Omron CX-Programmer project NuevoProyecto (CX-Programmer 9.50)

# PLC NewPLC1: CQM1 CPU21

## Program P5 (no task)
Local symbols
A 100.00 BOOL
ACP 100.07 BOOL
AL1 101.00 BOOL
AL2 101.01 BOOL
B 100.01 BOOL
Etapa_0 10.00 BOOL
Etapa_1 10.01 BOOL
Etapa_2 10.02 BOOL
Etapa_3 10.03 BOOL
Etapa_4 10.04 BOOL
Etapa_5 10.05 BOOL
Etapa_6 10.06 BOOL
Etapa_7 10.07 BOOL
Etapa_8 10.08 BOOL
FC1 0.03 BOOL
FC2 0.04 BOOL
LC 100.06 BOOL
LR_1 100.02 BOOL
LR_2 100.03 BOOL
LV1 100.04 BOOL
LV2 100.05 BOOL
S_1 0.01 BOOL
S_2 0.02 BOOL
T_0 15.00 BOOL
m 0.00 BOOL

### Section Sección1_Programa_principal
; Programa principal (Etapas 0 ... 8)

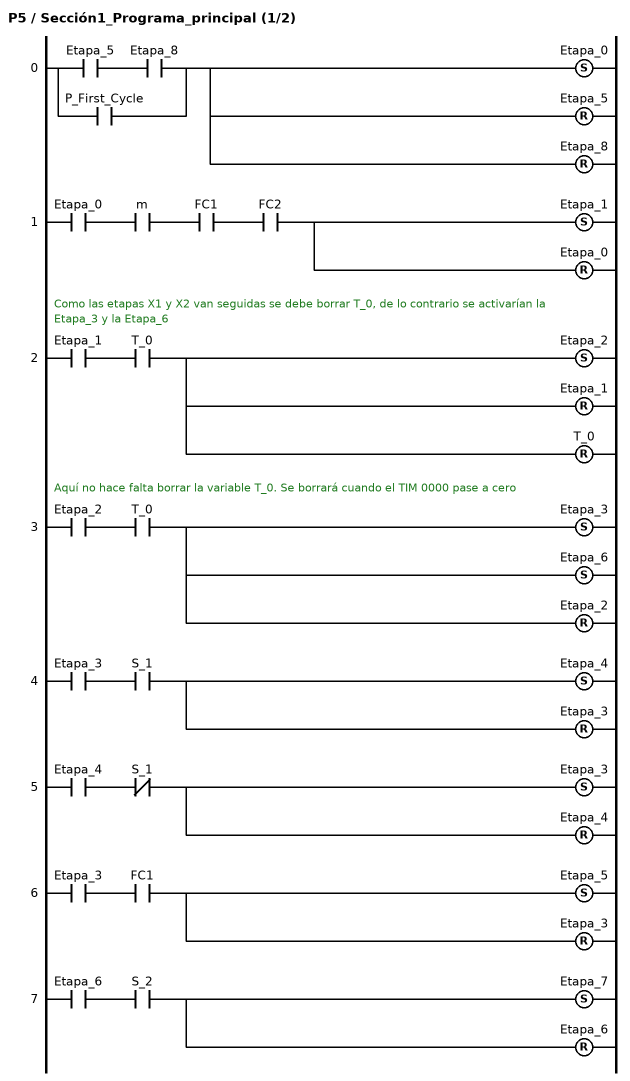
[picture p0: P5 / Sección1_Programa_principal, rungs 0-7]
; rung 0
LD Etapa_5
AND Etapa_8
OR P_First_Cycle
SET Etapa_0
RSET Etapa_5
RSET Etapa_8
; rung 1
LD Etapa_0
AND m
AND FC1
AND FC2
SET Etapa_1
RSET Etapa_0
; rung 2: Como las etapas X1 y X2 van seguidas se debe borrar T_0, de lo contrario se activarían la Etapa_3 y la Etapa_6
LD Etapa_1
AND T_0
SET Etapa_2
RSET Etapa_1
RSET T_0
; rung 3: Aquí no hace falta borrar la variable T_0. Se borrará cuando el TIM 0000 pase a cero
LD Etapa_2
AND T_0
SET Etapa_3
SET Etapa_6
RSET Etapa_2
; rung 4
LD Etapa_3
AND S_1
SET Etapa_4
RSET Etapa_3
; rung 5
LD Etapa_4
ANDNOT S_1
SET Etapa_3
RSET Etapa_4
; rung 6
LD Etapa_3
AND FC1
SET Etapa_5
RSET Etapa_3
; rung 7
LD Etapa_6
AND S_2
SET Etapa_7
RSET Etapa_6

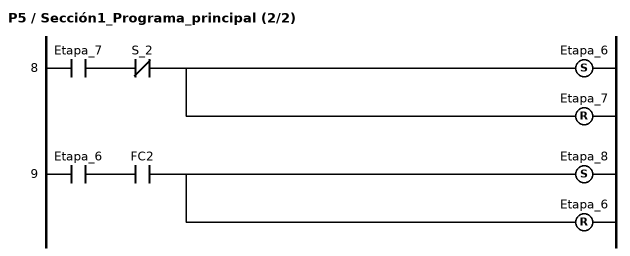
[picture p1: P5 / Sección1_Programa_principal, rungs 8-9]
; rung 8
LD Etapa_7
ANDNOT S_2
SET Etapa_6
RSET Etapa_7
; rung 9
LD Etapa_6
AND FC2
SET Etapa_8
RSET Etapa_6

### Section Sección2_Temporizador

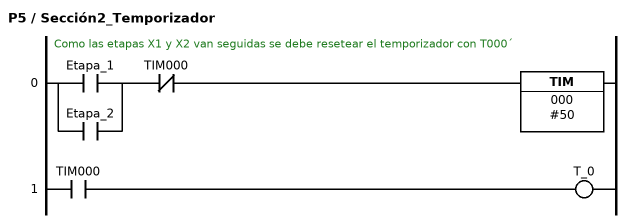
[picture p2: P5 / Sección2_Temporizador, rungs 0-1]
; rung 0: Como las etapas X1 y X2 van seguidas se debe resetear el temporizador con T000´
LD Etapa_1
OR Etapa_2
ANDNOT TIM000
TIM 000 #50
; rung 1
LD TIM000
OUT T_0

### Section Sección3_Salidas

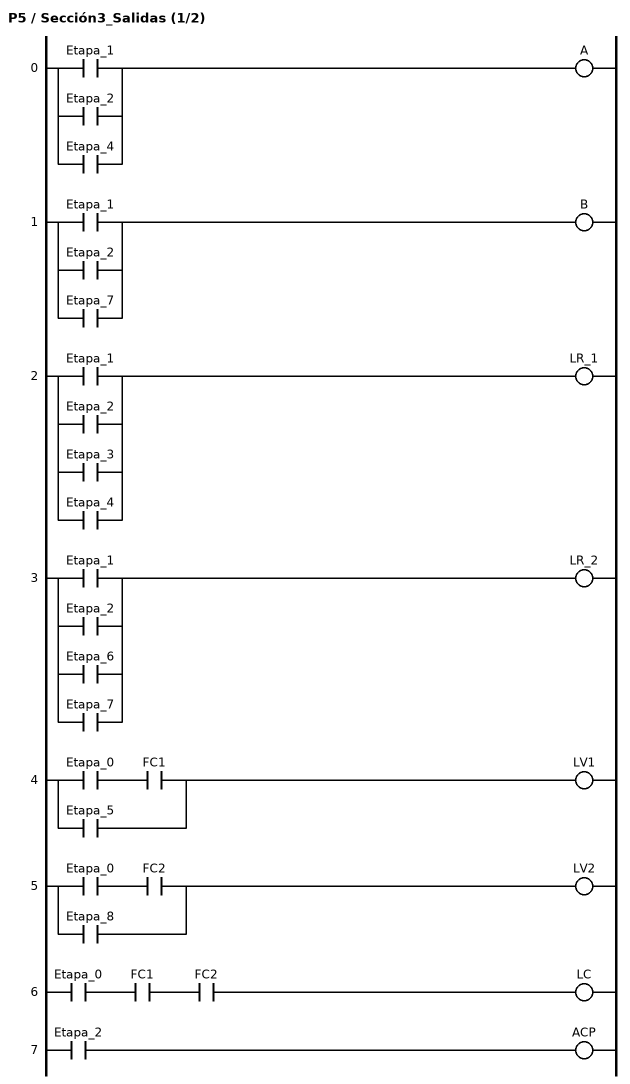
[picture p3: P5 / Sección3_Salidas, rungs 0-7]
; rung 0
LD Etapa_1
OR Etapa_2
OR Etapa_4
OUT A
; rung 1
LD Etapa_1
OR Etapa_2
OR Etapa_7
OUT B
; rung 2
LD Etapa_1
OR Etapa_2
OR Etapa_3
OR Etapa_4
OUT LR_1
; rung 3
LD Etapa_1
OR Etapa_2
OR Etapa_6
OR Etapa_7
OUT LR_2
; rung 4
LD Etapa_0
AND FC1
OR Etapa_5
OUT LV1
; rung 5
LD Etapa_0
AND FC2
OR Etapa_8
OUT LV2
; rung 6
LD Etapa_0
AND FC1
AND FC2
OUT LC
; rung 7
LD Etapa_2
OUT ACP

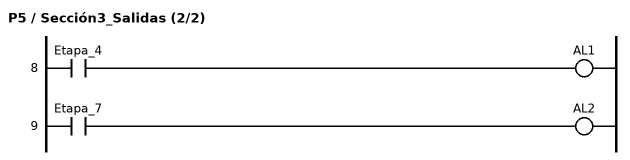
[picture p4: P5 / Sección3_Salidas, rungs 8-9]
; rung 8
LD Etapa_4
OUT AL1
; rung 9
LD Etapa_7
OUT AL2

### Section Sección4_END
; rung 0: Fin de programa
END(01)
